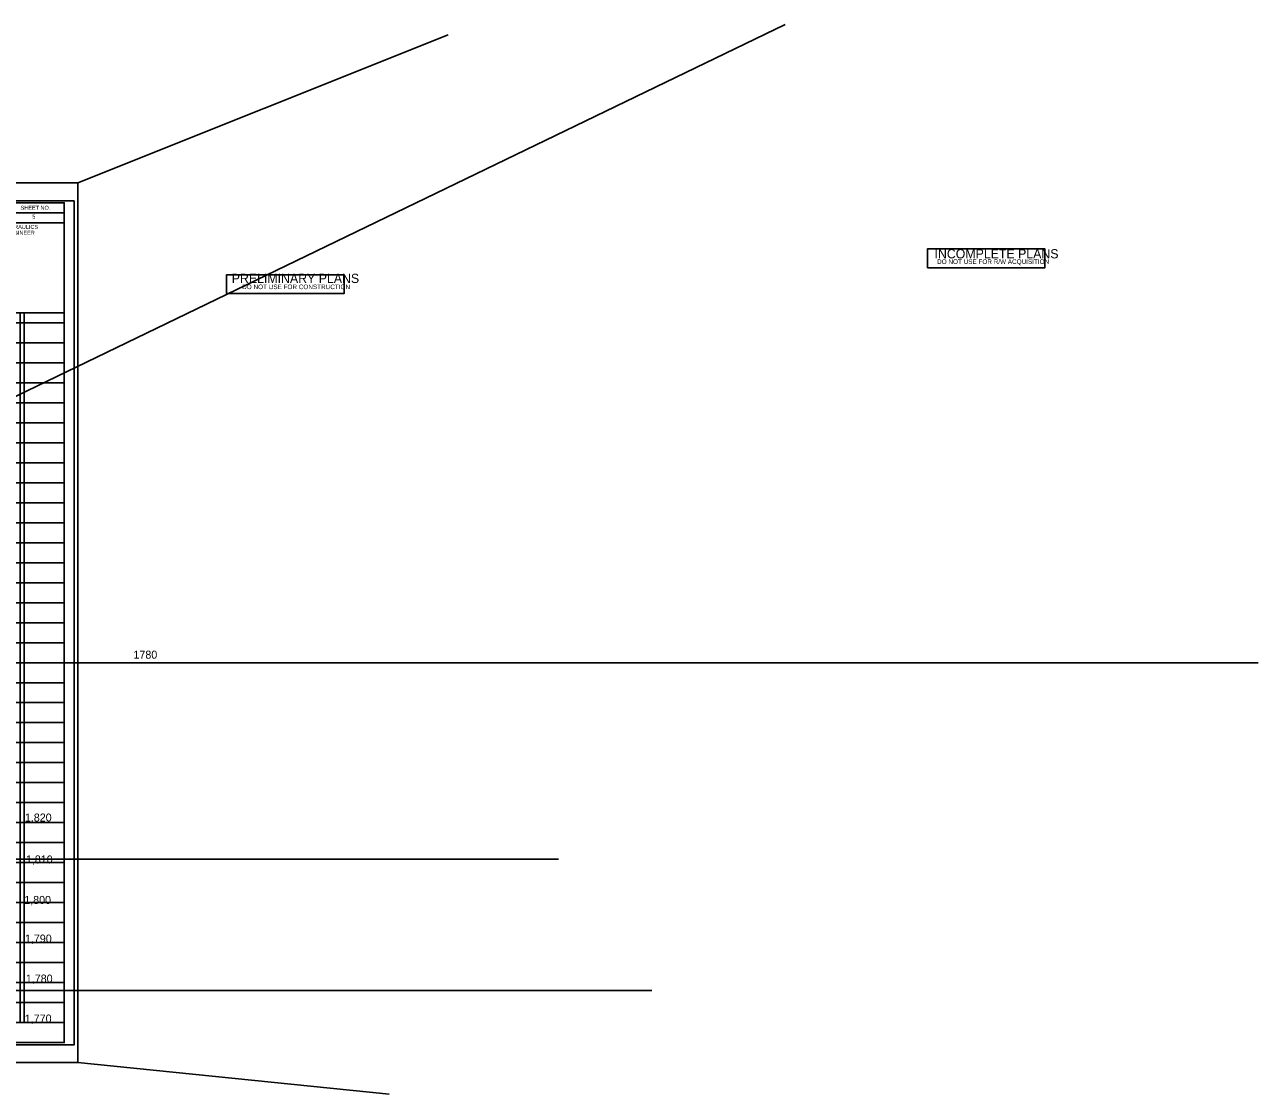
# Model space of a CAD drawing. Extents: x 572269 to 579912, y -56875 to -49627.
# Drawn here: x 575285 to 576827, y -53887 to -52550 of the extents above; entities that cross this region are included whole.
import ezdxf

# ---------------------------------------------------------------- set-up
doc = ezdxf.new("R2010")
doc.units = 0
for name, color, linetype in [('Exist Vertical Profile Vertical Axis Label', 7, 'Continuous'), ('Scratch_Level_3', 7, 'Continuous'), ('Scratch_Level_5', 7, 'Continuous'), ('Scratch_Level_6', 7, 'Continuous'), ('Sheet Cutting Line CELL', 7, 'Continuous'), ('Sheet DOT Grid CELL', 7, 'Continuous'), ('Sheet Plot Border Inside CELL', 7, 'Continuous'), ('Sheet Plot Border Outside CELL', 7, 'Continuous'), ('Sheet Profile CELL', 7, 'Continuous'), ('Sheet Profile Grid Major CELL', 7, 'Continuous'), ('Sheet Profile Grid Middle CELL', 7, 'Continuous'), ('Sheet Profile Grid Minor CELL', 7, 'Continuous'), ('Sheet Sticker Incomplete CELL', 7, 'Continuous'), ('Sheet Sticker Preliminary CELL', 7, 'Continuous')]:
    doc.layers.add(name, color=color, linetype=linetype)

# ---------------------------------------------------------------- blocks, each defined once
blk = doc.blocks.new('STICKER PRELIMINARY PLANS')
at = {"layer": 'Sheet Sticker Preliminary CELL'}
blk.add_lwpolyline([(0, -0.47), (0, 0), (2.94, 0), (2.94, -0.47)], close=True, dxfattribs=at)
for s, height, p in [('PRELIMINARY PLANS', 0.2304, (0.13, -0.207)), ('DO NOT USE FOR CONSTRUCTION', 0.1152, (0.392, -0.361))]:
    blk.add_text(s, height=height, dxfattribs=at).set_placement(p)
blk = doc.blocks.new('STICKER INCOMPLETE PLANS')
at = {"layer": 'Sheet Sticker Incomplete CELL'}
blk.add_lwpolyline([(0, -0.47), (0, 0), (2.94, 0), (2.94, -0.47)], close=True, dxfattribs=at)
for s, height, p in [('INCOMPLETE PLANS', 0.2304, (0.179, -0.236)), ('DO NOT USE FOR R/W ACQUISITION', 0.1152, (0.244, -0.375))]:
    blk.add_text(s, height=height, dxfattribs=at).set_placement(p)
blk = doc.blocks.new('PROFILE SHEET SINGLE')
at = {"layer": 'Sheet Cutting Line CELL'}
for p, q in [((30.34, 21.5), (-3.34, 21.5)), ((-3.34, -0.5), (30.34, -0.5))]:
    blk.add_line(p, q, dxfattribs=at)
at = {"layer": 'Sheet DOT Grid CELL'}
for p, q in [((0, 17.5), (30, 17.5)), ((0, 16.5), (30, 16.5)), ((0, 15.5), (30, 15.5)), ((0, 14.5), (30, 14.5)), ((0, 13.5), (30, 13.5)), ((0, 12.5), (30, 12.5)), ((0, 11.5), (30, 11.5)), ((0, 10.5), (30, 10.5)), ((0, 9.5), (30, 9.5)), ((0, 8.5), (30, 8.5)), ((0, 7.5), (30, 7.5)), ((0, 6.5), (30, 6.5)), ((0, 5.5), (30, 5.5)), ((0, 4.5), (30, 4.5)), ((0, 3.5), (30, 3.5)), ((0, 2.5), (30, 2.5)), ((0, 1.5), (30, 1.5))]:
    blk.add_line(p, q, dxfattribs=at)
at = {"layer": 'Sheet Plot Border Inside CELL'}
blk.add_lwpolyline([(30.25, 21.051), (-3.08, 21.051), (-3.08, -0.051), (30.25, -0.051)], close=True, dxfattribs=at)
at = {"layer": 'Sheet Plot Border Outside CELL'}
blk.add_lwpolyline([(30.34, 21.5), (-3.34, 21.5), (-3.34, -0.5), (30.34, -0.5)], close=True, dxfattribs=at)
at = {"layer": 'Sheet Profile CELL'}
for p, q in [((25.999, 20.749), (30, 20.749)), ((30, 0.5), (0, 0.5))]:
    blk.add_line(p, q, dxfattribs=at)
for points in [[(30, 21), (0, 21), (0, 0), (30, 0)], [(25.999, 21), (30, 21), (30, 20.499), (25.999, 20.499)], [(28, 20.499), (30, 20.499), (30, 18.249), (28, 18.249)]]:
    blk.add_lwpolyline(points, close=True, dxfattribs=at)
at = {"layer": 'Sheet Profile Grid Major CELL'}
for points in [[(30, 17.5), (0, 17.5), (0, 18.5), (25.999, 18.5)], [(29, 18.249), (29, 0.5), (30, 0.5)], [(30, 15.5), (0, 15.5), (0, 16.5), (30, 16.5)], [(30, 13.5), (0, 13.5), (0, 14.5), (30, 14.5)], [(30, 11.5), (0, 11.5), (0, 12.5), (30, 12.5)], [(30, 9.5), (0, 9.5), (0, 10.5), (30, 10.5)], [(30, 7.5), (0, 7.5), (0, 8.5), (30, 8.5)], [(30, 5.5), (0, 5.5), (0, 6.5), (30, 6.5)], [(30, 3.5), (0, 3.5), (0, 4.5), (30, 4.5)], [(30, 1.5), (0, 1.5), (0, 2.5), (30, 2.5)]]:
    blk.add_lwpolyline(points, dxfattribs=at)
at = {"layer": 'Sheet Profile Grid Middle CELL'}
for points in [[(25.999, 19), (0, 19), (0, 17.999), (30, 17.999)], [(30, 17), (0, 17), (0, 16), (30, 16)], [(30, 15), (0, 15), (0, 14), (30, 14)], [(30, 13), (0, 13), (0, 12), (30, 12)], [(30, 11), (0, 11), (0, 10), (30, 10)], [(30, 9), (0, 9), (0, 8), (30, 8)], [(30, 7), (0, 7), (0, 6), (30, 6)], [(30, 5), (0, 5), (0, 4), (30, 4)], [(30, 3), (0, 3), (0, 2), (30, 2)], [(30, 1), (0, 1)]]:
    blk.add_lwpolyline(points, dxfattribs=at)
at = {"layer": 'Sheet Profile Grid Minor CELL'}
blk.add_lwpolyline([(28.9, 18.249), (28.9, 0.5), (29.1, 0.5)], dxfattribs=at)
at = {"layer": 'Sheet Profile CELL'}
for s, p in [('SHEET NO.', (28.906, 20.824)), ('HYDRAULICS', (28.456, 20.345)), ('ENGINEER', (28.541, 20.198))]:
    blk.add_text(s, height=0.1, dxfattribs=at).set_placement(p)

msp = doc.modelspace()

# ---------------------------------------------------------------- linework, layer by layer
at = {"layer": 'Scratch_Level_3'}
for p, q in [((575351.7, -52747.7), (575814.2, -52562.8)), ((574584.7, -53757.7), (575984.2, -53757.7)), ((575351.7, -53847.7), (575740.7, -53887.3))]:
    msp.add_line(p, q, dxfattribs=at)
at = {"layer": 'Scratch_Level_5'}
for p, q in [((574594.8, -53593.5), (575952.2, -53593.5)), ((574584.7, -53757.7), (576068.7, -53757.7))]:
    msp.add_line(p, q, dxfattribs=at)
at = {"layer": 'Scratch_Level_6'}
for p, q in [((574584.7, -53347.7), (576235.4, -52550.1)), ((576826.8, -53347.7), (572993.9, -53347.7))]:
    msp.add_line(p, q, dxfattribs=at)

# ---------------------------------------------------------------- block references
at = {"layer": 'Sheet Cutting Line CELL', "xscale": 50, "yscale": 50}
for name, p in [('PROFILE SHEET SINGLE', (573834.7, -53822.7)), ('STICKER INCOMPLETE PLANS', (576413.2, -52830.5)), ('STICKER PRELIMINARY PLANS', (575537.4, -52862.7))]:
    msp.add_blockref(name, p, dxfattribs=at)

# ---------------------------------------------------------------- texts
at = {"layer": 'Exist Vertical Profile Vertical Axis Label'}
for s, p in [('1,820', (575285.4, -53546.3)), ('1,810', (575286.7, -53598.7)), ('1,800', (575284.6, -53649.3)), ('1,790', (575285.5, -53697.6)), ('1,780', (575286.6, -53747.6)), ('1,770', (575285.3, -53797.6))]:
    msp.add_text(s, height=10, dxfattribs=at).set_placement(p)
at = {"layer": 'Scratch_Level_6'}
msp.add_text('1780', height=10, dxfattribs=at).set_placement((575421.1, -53342.7))
at = {"layer": 'Sheet Profile CELL'}
msp.add_text('5', height=5, dxfattribs=at).set_placement((575294.7, -52792.6))

doc.saveas('drawing.dxf')
